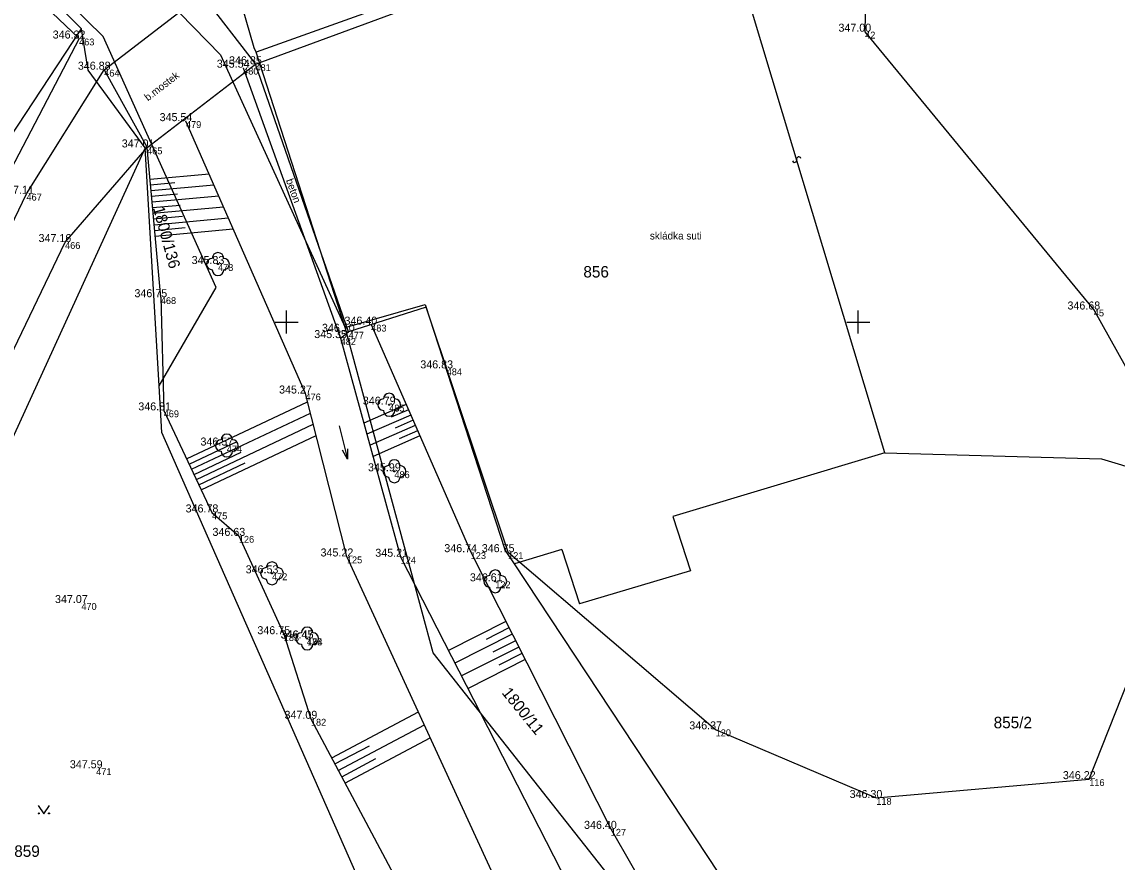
# Model space of a CAD drawing. Extents: x -614046 to -613877, y -1156755 to -1156623.
# Drawn here: x -614009.26 to -613970.95, y -1156678.89 to -1156649.5 of the extents above; entities that cross this region are included whole.
import ezdxf

# ---------------------------------------------------------------- set-up
doc = ezdxf.new("R2010")
doc.units = 0
for name, color, linetype in [('1-bod', 7, 'Continuous'), ('11-zpevněné plochy', 7, 'Continuous'), ('12-nezpevněné plochy', 7, 'Continuous'), ('14-terénní hrany', 7, 'Continuous'), ('15-šrafy', 7, 'Continuous'), ('16-vodní tok', 7, 'Continuous'), ('2-bod výška', 7, 'Continuous'), ('22-stromy', 7, 'Continuous'), ('3-bod číslo', 7, 'Continuous'), ('36-Značky kultur', 7, 'Continuous'), ('40-popisy povrchů', 7, 'Continuous'), ('45-popis vodní tok', 7, 'Continuous'), ('50-hranice parcel KN', 7, 'Continuous'), ('61-hektarová síť', 7, 'Continuous'), ('7-plot', 7, 'Continuous')]:
    doc.layers.add(name, color=color, linetype=linetype)

# ---------------------------------------------------------------- blocks, each defined once
blk = doc.blocks.new('3.13_1')
at = {"layer": '22-stromy'}
blk.add_circle((0, 0), 0.05, dxfattribs=at)
for centre, start, end in [((0, 0.5), 0, 180), ((-0.5, 0), 90, 270), ((0.5, 0), 270, 90), ((0, -0.5), 180, 0)]:
    blk.add_arc(centre, 0.5, start, end, dxfattribs=at)
blk = doc.blocks.new('8.02')
at = {"layer": '45-popis vodní tok'}
blk.add_line((-3, 0), (0, 0), dxfattribs=at)
blk.add_lwpolyline([(-0.876, 0.23), (0, 0), (-0.876, -0.23)], dxfattribs=at)
blk = doc.blocks.new('3.14')
at = {"layer": '36-Značky kultur'}
blk.add_lwpolyline([(-0.5, 0.75), (0, 0), (0.5, 0.75)], dxfattribs=at)
for centre in [(-0.45, 0.05), (0.449, 0.05)]:
    blk.add_circle(centre, 0.05, dxfattribs=at)
blk = doc.blocks.new('2.18')
at = {"layer": '50-hranice parcel KN'}
for centre, start, end in [((0, 0.188), 90, 270), ((0, -0.187), 270, 90)]:
    blk.add_arc(centre, 0.187, start, end, dxfattribs=at)
blk = doc.blocks.new('POINT_DISPLAY')
blk.add_line((0, 0), (0, 0))

msp = doc.modelspace()

# ---------------------------------------------------------------- linework, layer by layer
at = {"layer": '11-zpevněné plochy'}
for p, q in [((-614006.38, -1156651.17), (-614004.88, -1156653.89)), ((-614004.88, -1156653.89), (-614001.09, -1156650.98))]:
    msp.add_line(p, q, dxfattribs=at)
for points in [[(-614006.38, -1156651.17), (-614002.96, -1156648.54), (-614001.09, -1156650.98)], [(-613998.11, -1156660.56), (-613997.83, -1156660.34)]]:
    msp.add_lwpolyline(points, dxfattribs=at)
at = {"layer": '12-nezpevněné plochy'}
for p, q in [((-613979.76, -1156649.84), (-613979.64, -1156643.67)), ((-613971.76, -1156659.56), (-613979.76, -1156649.84)), ((-613968.23, -1156665.91), (-613971.76, -1156659.56)), ((-613992.25, -1156668.05), (-613984.99, -1156674.25)), ((-613971.92, -1156675.99), (-613968.97, -1156668.5)), ((-613984.99, -1156674.25), (-613979.37, -1156676.65)), ((-613979.37, -1156676.65), (-613971.92, -1156675.99))]:
    msp.add_line(p, q, dxfattribs=at)
for points in [[(-614020.49, -1156678.89), (-614014.45, -1156666.65), (-614009.1, -1156655.51), (-614006.38, -1156651.17)], [(-614017.81, -1156680.62), (-614013.12, -1156668.39), (-614007.75, -1156657.2), (-614004.88, -1156653.89)]]:
    msp.add_lwpolyline(points, dxfattribs=at)
at = {"layer": '14-terénní hrany'}
msp.add_line((-614004.4, -1156659.13), (-614004.88, -1156653.89), dxfattribs=at)
for points in [[(-614004.4, -1156659.13), (-614004.3, -1156663.09), (-614002.61, -1156666.66), (-614001.67, -1156667.48), (-614000.1, -1156670.92), (-613999.15, -1156673.88), (-613995.97, -1156679.86), (-614001.33, -1156681.8), (-614006.87, -1156684.07)], [(-613997.04, -1156660.09), (-613993.56, -1156668.05), (-613988.66, -1156677.73), (-613984.98, -1156684.14), (-613979.93, -1156688.52), (-613976.6, -1156692.93), (-613968.24, -1156698.72), (-613963.28, -1156701.99), (-613959.08, -1156705.39), (-613955.46, -1156707.77), (-613951.07, -1156711.08), (-613944.86, -1156716.28)]]:
    msp.add_lwpolyline(points, dxfattribs=at)
at = {"layer": '15-šrafy'}
for p, q in [((-614004.778, -1156654.998), (-614002.713, -1156654.809)), ((-614004.76, -1156655.197), (-614003.908, -1156655.119)), ((-614004.742, -1156655.397), (-614002.544, -1156655.195)), ((-614004.724, -1156655.596), (-614003.818, -1156655.513)), ((-614004.705, -1156655.795), (-614002.375, -1156655.581)), ((-614004.687, -1156655.994), (-614003.728, -1156655.906)), ((-614004.669, -1156656.193), (-614002.205, -1156655.968)), ((-614004.651, -1156656.392), (-614003.639, -1156656.3)), ((-614004.633, -1156656.592), (-614002.036, -1156656.354)), ((-614004.614, -1156656.791), (-614003.549, -1156656.693)), ((-614004.596, -1156656.99), (-614001.866, -1156656.74)), ((-614003.496, -1156664.788), (-613999.267, -1156662.786)), ((-613995.818, -1156662.886), (-613997.294, -1156663.531)), ((-613995.738, -1156663.069), (-613996.339, -1156663.332)), ((-614003.325, -1156665.15), (-613999.167, -1156663.181)), ((-613995.658, -1156663.252), (-613997.187, -1156663.921)), ((-613995.577, -1156663.435), (-613996.2, -1156663.707)), ((-614003.154, -1156665.511), (-613999.066, -1156663.576)), ((-613995.497, -1156663.619), (-613997.08, -1156664.311)), ((-613995.417, -1156663.802), (-613996.061, -1156664.083)), ((-614003.411, -1156664.969), (-614001.733, -1156664.175)), ((-614002.983, -1156665.873), (-613998.966, -1156663.971)), ((-613995.337, -1156663.985), (-613996.973, -1156664.7)), ((-614003.239, -1156665.33), (-614001.59, -1156664.55)), ((-614003.068, -1156665.692), (-614001.447, -1156664.925)), ((-613992.33, -1156670.48), (-613994.33, -1156671.49)), ((-613992.22, -1156670.7), (-613993.02, -1156671.1)), ((-613992.11, -1156670.92), (-613994.11, -1156671.93)), ((-613991.99, -1156671.15), (-613992.79, -1156671.55)), ((-613991.88, -1156671.37), (-613993.88, -1156672.38)), ((-613991.65, -1156671.81), (-613993.65, -1156672.82)), ((-613991.77, -1156671.59), (-613992.57, -1156672)), ((-613998.42, -1156675.24), (-613995.39, -1156673.63)), ((-613998.19, -1156675.69), (-613995.18, -1156674.09)), ((-613997.96, -1156676.13), (-613994.98, -1156674.54)), ((-613998.31, -1156675.46), (-613997.1, -1156674.82)), ((-613998.07, -1156675.91), (-613996.88, -1156675.27))]:
    msp.add_line(p, q, dxfattribs=at)
at = {"layer": '16-vodní tok'}
for points in [[(-614001.52, -1156651.1), (-613998.11, -1156660.56), (-613996.01, -1156668.21), (-613990.4, -1156679.18), (-613986.72, -1156685.51), (-613977.75, -1156695.09), (-613969.35, -1156700.93), (-613963.95, -1156705.16), (-613955.95, -1156708.89), (-613951.7, -1156712.2), (-613945.56, -1156718.87), (-613945.478, -1156720.252)], [(-613947.4, -1156720.89), (-613951.41, -1156714.98), (-613956.19, -1156710.22), (-613963.8, -1156706.47), (-613969.59, -1156701.81), (-613978.15, -1156696.55), (-613986.41, -1156688.9), (-613987.27, -1156689.02), (-613988.53, -1156686.84), (-613992.1, -1156680.8), (-613997.89, -1156668.2), (-613999.34, -1156662.5), (-614003.52, -1156652.97)]]:
    msp.add_lwpolyline(points, dxfattribs=at)
at = {"layer": '50-hranice parcel KN'}
for points in [[(-613973.51, -1156640.7), (-614001.06, -1156650.56)], [(-614007.998, -1156644.803), (-614002.31, -1156650.65)], [(-613979.07, -1156664.57), (-613984.82, -1156645.46)], [(-614009.915, -1156646.57), (-614006.42, -1156650.01)], [(-614007.18, -1156649.74), (-614010.147, -1156646.784)], [(-614001.13, -1156650.4), (-614002.21, -1156646.69)], [(-614010.81, -1156655.26), (-614007.18, -1156649.74)], [(-614006.94, -1156651.19), (-614007.18, -1156649.74)], [(-614002.46, -1156658.79), (-614006.42, -1156650.01)], [(-614001.06, -1156650.56), (-614001.13, -1156650.4)], [(-614002.31, -1156650.65), (-613997.95, -1156660.19)], [(-613997.95, -1156660.19), (-614001.06, -1156650.56)], [(-614004.95, -1156653.9), (-614006.94, -1156651.19)], [(-614004.95, -1156653.9), (-614017.72, -1156681.82)], [(-614004.46, -1156662.23), (-614004.95, -1156653.9)], [(-614004.46, -1156662.23), (-614002.46, -1156658.79)], [(-613997.95, -1156660.19), (-613995.15, -1156659.39)], [(-613995.15, -1156659.39), (-613992.36, -1156667.96)], [(-613994.87, -1156671.57), (-613997.95, -1156660.19)], [(-614004.36, -1156663.86), (-614004.46, -1156662.23)], [(-613996.36, -1156682.02), (-614004.36, -1156663.86)], [(-613979.07, -1156664.57), (-613986.49, -1156666.8)], [(-613979.07, -1156664.57), (-613971.49, -1156664.79)], [(-613971.49, -1156664.79), (-613963.85, -1156667.08)], [(-613986.49, -1156666.8), (-613985.87, -1156668.7)], [(-613992.03, -1156668.46), (-613992.36, -1156667.96)], [(-613990.37, -1156667.96), (-613992.03, -1156668.46)], [(-613990.37, -1156667.96), (-613989.75, -1156669.86)], [(-613981.5, -1156684.4), (-613992.03, -1156668.46)], [(-613985.87, -1156668.7), (-613989.75, -1156669.86)], [(-613979.96, -1156690.49), (-613994.87, -1156671.57)]]:
    msp.add_lwpolyline(points, dxfattribs=at)
at = {"layer": '61-hektarová síť'}
for points in [[(-614000, -1156660.4), (-614000, -1156660), (-614000, -1156659.6)], [(-613980, -1156660.4), (-613980, -1156660), (-613980, -1156659.6)], [(-614000.4, -1156660), (-614000, -1156660), (-613999.6, -1156660)], [(-613980.4, -1156660), (-613980, -1156660), (-613979.6, -1156660)]]:
    msp.add_lwpolyline(points, dxfattribs=at)
at = {"layer": '7-plot'}
for points in [[(-614001.09, -1156650.98), (-613963.33, -1156637.08), (-613958.98, -1156643.72), (-613952.52, -1156653.05), (-613956.95, -1156655.7)], [(-614009.63, -1156647.8), (-614007.26, -1156650.08)], [(-614007.26, -1156650.08), (-614014.86, -1156664.63), (-614021.21, -1156676.7), (-614022.48, -1156676.17)], [(-613995.12, -1156659.48), (-613997.83, -1156660.34), (-614001.09, -1156650.98)], [(-613992.25, -1156668.05), (-613995.12, -1156659.48)]]:
    msp.add_lwpolyline(points, dxfattribs=at)

# ---------------------------------------------------------------- block references
at = {"layer": '1-bod'}
for p in [(-614007.26, -1156650.08), (-613979.76, -1156649.84), (-614006.38, -1156651.17), (-614001.52, -1156651.1), (-614001.09, -1156650.98), (-614003.52, -1156652.97), (-614004.88, -1156653.89), (-614009.1, -1156655.51), (-614007.75, -1156657.2), (-614002.4, -1156657.97), (-614004.4, -1156659.13), (-613971.76, -1156659.56), (-613997.83, -1156660.34), (-613997.04, -1156660.09), (-613998.11, -1156660.56), (-613994.4, -1156661.62), (-613999.34, -1156662.5), (-614004.3, -1156663.09), (-613996.41, -1156662.89), (-614002.09, -1156664.32), (-613996.23, -1156665.22), (-614002.61, -1156666.66), (-614001.67, -1156667.48), (-613993.56, -1156668.05), (-613992.25, -1156668.05), (-613997.89, -1156668.2), (-613996.01, -1156668.21), (-614000.51, -1156668.79), (-613992.7, -1156669.07), (-614007.18, -1156669.83), (-614000.1, -1156670.92), (-613999.29, -1156671.07), (-613999.28, -1156671.07), (-613999.15, -1156673.88), (-613984.99, -1156674.25), (-614006.66, -1156675.61), (-613971.92, -1156675.99), (-613979.37, -1156676.65), (-613988.66, -1156677.73)]:
    msp.add_blockref('POINT_DISPLAY', p, dxfattribs=at)
at = {"layer": '22-stromy', "xscale": 0.4, "yscale": 0.4000000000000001}
for p in [(-614002.4, -1156657.97), (-613996.41, -1156662.89), (-614002.09, -1156664.32), (-613996.23, -1156665.22), (-614000.51, -1156668.79), (-613992.7, -1156669.07), (-613999.28, -1156671.07)]:
    msp.add_blockref('3.13_1', p, dxfattribs=at)
at = {"layer": '36-Značky kultur', "xscale": 0.4, "yscale": 0.4000000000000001}
msp.add_blockref('3.14', (-614008.49, -1156677.21), dxfattribs=at)
at = {"layer": '45-popis vodní tok', "xscale": 0.4, "yscale": 0.39999999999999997, "rotation": -76.16717264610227}
msp.add_blockref('8.02', (-613997.87, -1156664.8), dxfattribs=at)
at = {"layer": '50-hranice parcel KN', "xscale": 0.4, "yscale": 0.39999999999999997, "rotation": -73.2540062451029}
msp.add_blockref('2.18', (-613982.155, -1156654.317), dxfattribs=at)

# ---------------------------------------------------------------- texts
at = {"layer": '2-bod výška'}
for s, p in [('347.00 ', (-613980.693, -1156649.84)), ('346.32 ', (-614008.182, -1156650.08)), ('345.54 ', (-614002.442, -1156651.1)), ('346.85 ', (-614002.012, -1156650.98)), ('346.88 ', (-614007.302, -1156651.17)), ('345.54 ', (-614004.442, -1156652.97)), ('347.01 ', (-614005.767, -1156653.89)), ('347.11 ', (-614009.987, -1156655.51)), ('347.16 ', (-614008.678, -1156657.2)), ('345.83 ', (-614003.322, -1156657.97)), ('346.75 ', (-614005.322, -1156659.13)), ('346.68 ', (-613972.682, -1156659.56)), ('346.10 ', (-613998.763, -1156660.34)), ('346.40 ', (-613997.973, -1156660.09)), ('345.35 ', (-613999.032, -1156660.56)), ('346.83 ', (-613995.322, -1156661.62)), ('345.27 ', (-614000.262, -1156662.5)), ('346.79 ', (-613997.332, -1156662.89)), ('346.81 ', (-614005.187, -1156663.09)), ('346.57 ', (-614003.012, -1156664.32)), ('345.99 ', (-613997.152, -1156665.22)), ('346.78 ', (-614003.532, -1156666.66)), ('346.63 ', (-614002.592, -1156667.48)), ('345.22 ', (-613998.812, -1156668.2)), ('345.21 ', (-613996.897, -1156668.21)), ('346.74 ', (-613994.482, -1156668.05)), ('346.75 ', (-613993.172, -1156668.05)), ('346.53 ', (-614001.432, -1156668.79)), ('346.61 ', (-613993.587, -1156669.07)), ('347.07 ', (-614008.102, -1156669.83)), ('346.75 ', (-614001.022, -1156670.92)), ('346.47 ', (-614000.212, -1156671.07)), ('346.45 ', (-614000.202, -1156671.07)), ('347.09 ', (-614000.072, -1156673.88)), ('346.37 ', (-613985.912, -1156674.25)), ('347.59 ', (-614007.582, -1156675.61)), ('346.22 ', (-613972.842, -1156675.99)), ('346.30 ', (-613980.303, -1156676.65)), ('346.40 ', (-613989.593, -1156677.73))]:
    msp.add_text(s, height=0.28, dxfattribs=at).set_placement(p)
at = {"layer": '3-bod číslo'}
for s, p in [('463', (-614007.26, -1156650.32)), ('42', (-613979.76, -1156650.08)), ('464', (-614006.38, -1156651.41)), ('480', (-614001.52, -1156651.34)), ('481', (-614001.09, -1156651.22)), ('479', (-614003.52, -1156653.21)), ('465', (-614004.88, -1156654.13)), ('467', (-614009.1, -1156655.75)), ('466', (-614007.75, -1156657.44)), ('478', (-614002.4, -1156658.21)), ('468', (-614004.4, -1156659.37)), ('45', (-613971.76, -1156659.8)), ('477', (-613997.83, -1156660.58)), ('483', (-613997.04, -1156660.33)), ('482', (-613998.11, -1156660.8)), ('484', (-613994.4, -1156661.86)), ('476', (-613999.34, -1156662.74)), ('469', (-614004.3, -1156663.33)), ('485', (-613996.41, -1156663.13)), ('474', (-614002.09, -1156664.56)), ('486', (-613996.23, -1156665.46)), ('475', (-614002.61, -1156666.9)), ('126', (-614001.67, -1156667.72)), ('123', (-613993.56, -1156668.29)), ('121', (-613992.25, -1156668.29)), ('125', (-613997.89, -1156668.44)), ('124', (-613996.01, -1156668.45)), ('472', (-614000.51, -1156669.03)), ('122', (-613992.7, -1156669.31)), ('470', (-614007.18, -1156670.07)), ('183', (-614000.1, -1156671.16)), ('473', (-613999.29, -1156671.31)), ('184', (-613999.28, -1156671.31)), ('182', (-613999.15, -1156674.12)), ('120', (-613984.99, -1156674.49)), ('471', (-614006.66, -1156675.85)), ('116', (-613971.92, -1156676.23)), ('118', (-613979.37, -1156676.89)), ('127', (-613988.66, -1156677.97))]:
    msp.add_text(s, height=0.24, dxfattribs=at).set_placement(p)
at = {"layer": '40-popisy povrchů'}
for s, rotation, p in [('b.mostek', 37.5174, (-614004.85, -1156652.28)), ('beton', 289.8225, (-614000.027, -1156655.038))]:
    msp.add_text(s, height=0.26, rotation=rotation, dxfattribs=at).set_placement(p)
msp.add_text('skládka suti', height=0.26, dxfattribs=at).set_placement((-613987.29, -1156657.11))
at = {"layer": '50-hranice parcel KN'}
for s, rotation, p in [('1800/136', 285.1341, (-614004.676, -1156656.007)), ('1800/11', 309.1025, (-613992.491, -1156672.977))]:
    msp.add_text(s, height=0.4, rotation=rotation, dxfattribs=at).set_placement(p)
for s, p in [('856', (-613989.617, -1156658.44)), ('855/2', (-613975.263, -1156674.21)), ('859', (-614009.527, -1156678.71))]:
    msp.add_text(s, height=0.4, dxfattribs=at).set_placement(p)

doc.saveas('drawing.dxf')
